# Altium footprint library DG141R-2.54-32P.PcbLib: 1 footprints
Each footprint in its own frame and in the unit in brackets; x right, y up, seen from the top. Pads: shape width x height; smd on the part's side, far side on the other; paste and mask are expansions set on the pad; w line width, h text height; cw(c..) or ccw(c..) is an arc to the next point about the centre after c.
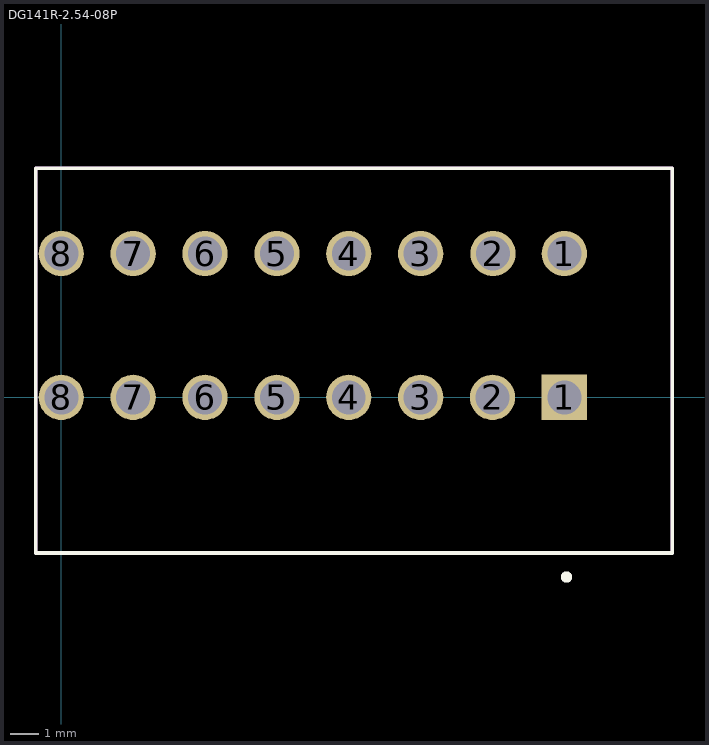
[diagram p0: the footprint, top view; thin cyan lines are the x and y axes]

## DG141R-2.54-08P [mm]
pads (16):
  rect 1.6x1.6 hole 1.2: 1(17.78,0)
  round 1.6 hole 1.2: 1(17.78,5.08) 2(15.24,0) 2(15.26,5.08) 3(12.7,0) 3(12.7,5.08) 4(10.16,0) 4(10.16,5.08) 5(7.62,0) 5(7.62,5.08) 6(5.08,0) 6(5.08,5.08) 7(2.54,0) 7(2.54,5.08) 8(0,0) 8(0,5.08)
Top Overlay:
  circle w0.2: c17.856,-6.35 r0.1
  lines w0.127: -0.9,-5.5 21.59,-5.5 21.59,8.1 -0.9,8.1 -0.9,-5.5
Mechanical 13:
  lines w0.127: -0.9,-5.5 21.59,-5.5 21.59,8.1 -0.9,8.1 -0.9,-5.5
3D body "DG141R-2.54-08P.stp": height 12.6, standoff -3.2, extent -1.066,-5.637 21.794,7.963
